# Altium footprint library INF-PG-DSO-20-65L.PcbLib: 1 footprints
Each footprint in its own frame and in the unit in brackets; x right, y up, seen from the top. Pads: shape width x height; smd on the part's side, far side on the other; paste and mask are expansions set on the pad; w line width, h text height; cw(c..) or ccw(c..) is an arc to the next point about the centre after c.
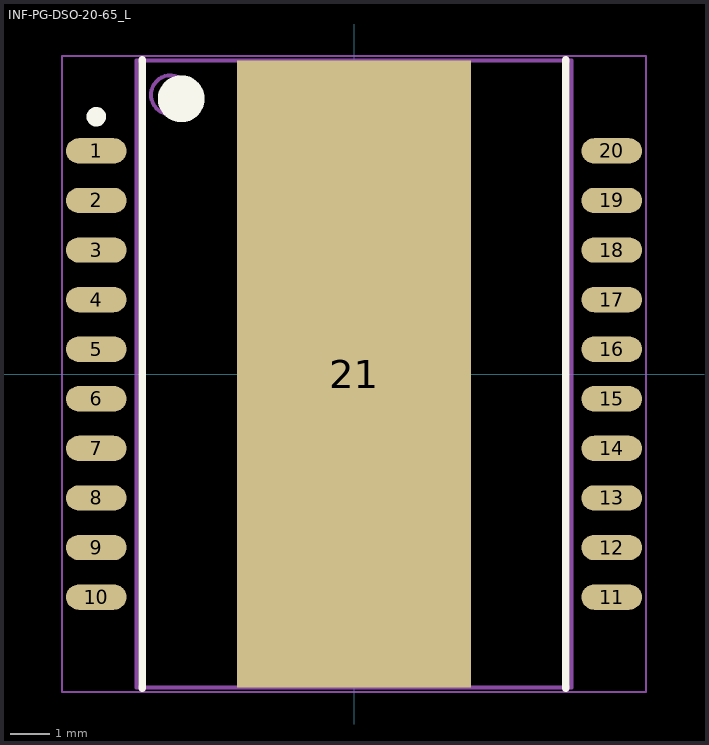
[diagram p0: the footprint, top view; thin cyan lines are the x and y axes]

## INF-PG-DSO-20-65_L [mm] "SOP, 20-Leads, Body 15.9x11mm, Pitch 1.27mm, Thermal Pad 16.05x6mm, IPC High Density"
height 3.5
pads (21):
  oval 1.55x0.65 smd: 1(-6.6,5.715) 2(-6.6,4.445) 3(-6.6,3.175) 4(-6.6,1.905) 5(-6.6,0.635) 6(-6.6,-0.635) 7(-6.6,-1.905) 8(-6.6,-3.175) 9(-6.6,-4.445) 10(-6.6,-5.715) 11(6.6,-5.715) 12(6.6,-4.445) 13(6.6,-3.175) 14(6.6,-1.905) 15(6.6,-0.635) 16(6.6,0.635) 17(6.6,1.905) 18(6.6,3.175) 19(6.6,4.445) 20(6.6,5.715)
  rect 6x16.05 smd: 21(0,0)
Top Overlay:
  circle w0.6: c-4.425,7.05 r0.3
  circle w0.25: c-6.6,6.59 r0.125
  lines w0.2: -5.425,-8.05 -5.425,8.05 ; 5.425,-8.05 5.425,8.05
Mechanical 13:
  circle w0.1: c-4.7,7.15 r0.5
  lines w0.1: -5.575,-8.025 5.575,-8.025 5.575,8.025 -5.575,8.025 -5.575,-8.025
Mechanical 15:
  lines w0.05: -7.475,-8.15 7.475,-8.15 7.475,8.15 -7.475,8.15 -7.475,-8.15
  lines w0.1: -0.5,0 0.5,0 ; 0,-0.5 0,0.5
3D body: height 3.5, standoff 0, extent -5.575,-8.025 5.575,8.025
